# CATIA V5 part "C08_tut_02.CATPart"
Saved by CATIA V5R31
Part number: Part1
Bounding box of the stored display mesh (mm): x -49.812 to 35, y -44.222 to 44.222, z 0 to 30
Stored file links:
  D:\PROJECTS\Project 2021\US EDITION\CATIA V5 6R 2021\Resources\Tutorial Files\c08_catia_v5_6r2021_tut\C08_tut_02.CATPart
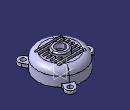
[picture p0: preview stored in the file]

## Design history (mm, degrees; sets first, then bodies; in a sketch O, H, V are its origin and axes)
Body1 (main body)
  Sketch1 on yz-plane, origin (0, 0, 0), H (0, 1, 0), V (0, 0, 1)
    line L1 (0, 0) -> (0, 25)
    line L2 (0, 25) -> (25, 25)
    point P2 (35, 25)
    line L3 (35, 15) -> (35, 0)
    point P3 (35, 0)
    line L4 (35, 0) -> (0, 0)
    reference intersected line E1 through (0, 0) direction (0, 1) from zx-plane
    axis line L5 (0, 41.2428) -> (0, -12.5007)
    point P4 (0, 41.2428)
    arc A1 centre (25, 15) radius 10 from (25, 25) to (35, 15) cw
    radius about axis P3 L5 = 35
    distance P2 P3 = 25
    radius A1 = 10
    horizontal: L2 H, L4 H
    coincidence: P3 H, L1 E1, P4 L1, L2 P2, L3 P2
    vertical: L3 V, L5 V
    tangency: A1 L2, A1 L3
  Shaft1: profile Sketch1, axis Sketch1.L5, angle 360
  Shell1: ExtOffset 0, Face face of Shaft1 from Sketch1.L4, IntOffset 3
  Sketch2 on face of Shaft1 from Sketch1.L4, origin (0, 0, 0), H (1, 0, 0), V (0, -1, 0)
    projected circle E1 centre (0, 0) radius 35 from edge [face of Shaft1 from Sketch1.L3 | face of Shaft1 from Sketch1.L4]
    projected arc E2 centre (0, 0) radius 35 from (-34.187, 7.5) to (-34.187, -7.5) ccw from edge [face of Shaft1 from Sketch1.L3 | face of Shaft1 from Sketch1.L4]
    point P1 (-34.187, 7.5)
    line L1 (-34.187, 7.5) -> (-42.5, 7.5)
    arc A1 centre (-42.5, 0) radius 7.5 from (-42.5, 7.5) to (-42.5, -7.5) ccw
    point P3 (-42.5, 0)
    line L2 (-42.5, -7.5) -> (-34.187, -7.5)
    point P5 (-34.187, -7.5)
    circle A2 centre (-42.5, 0) radius 3.75
    radius A1 = 7.5
    radius A2 = 3.75
    distance P3 V = 42.5
    coincidence: P1 E1, P3 H, P5 E1
    horizontal: L1 H, L2 H
    tangency: A1 L1, L2 A1
  Pad1: profile Sketch2, direction (0, 0, 1), length 5
  CircPattern1: of Pad1, instances 3, angular step 120 {= 360.0*1 deg/CircPattern1.AngularNumber}, axis from face of Shaft1 from Sketch1.L3
  Sketch3 on face of Shaft1 from Sketch1.L2, origin (0, 0, 25), H (1, 0, 0), V (0, 1, 0)
    point P1 (0, -18)
    line L1 (20, -19.75) -> (-20, -19.75)
    line L2 (-20, -16.25) -> (20, -16.25)
    point P5 (-20, -16.25)
    point P6 (20, -18)
    point P7 (-20, -18)
    arc A1 centre (20, -18) radius 1.75 from (20, -19.75) to (20, -16.25) ccw
    arc A2 centre (-20, -18) radius 1.75 from (-20, -16.25) to (-20, -19.75) ccw
    point P8 (-20, -16.25)
    axis line L3 (20, -18) -> (-20, -18)
    distance H P6 = 18
    distance L2 L1 = 3.5
    distance V P6 = 20
    coincidence: P1 V, A2 P5, P5 P8
    horizontal: L1 H, L2 H, L3 H
    equidistance: L1 L2 P1
    tangency: A1 L1, A2 L1, L2 A2, L2 A1
    symmetry: P7 P6 V
  Pocket1: profile Sketch3, direction (0, 0, -1), length 8
  RectPattern1: of Pocket1, direction 1 instances 7, spacing 6, along yz-plane
  Sketch4 on face of Shell1, origin (0, 0, 22), H (1, 0, 0), V (0, -1, 0)
    circle A1 centre (0, 0) radius 12.5
    radius A1 = 12.5
  Pad2: profile Sketch4, direction (0, 0, 1), length 8
  Sketch5 on face of Pad2, origin (0, 0, 22), H (1, 0, 0), V (0, -1, 0)
    circle A1 centre (0, 0) radius 7.5
    radius A1 = 7.5
  Pocket2: profile Sketch5, direction (0, 0, 1), length 8
  Fillet1: radius 2, on edge [end face of Pad2 | face of Pad2 from Sketch4.A1]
